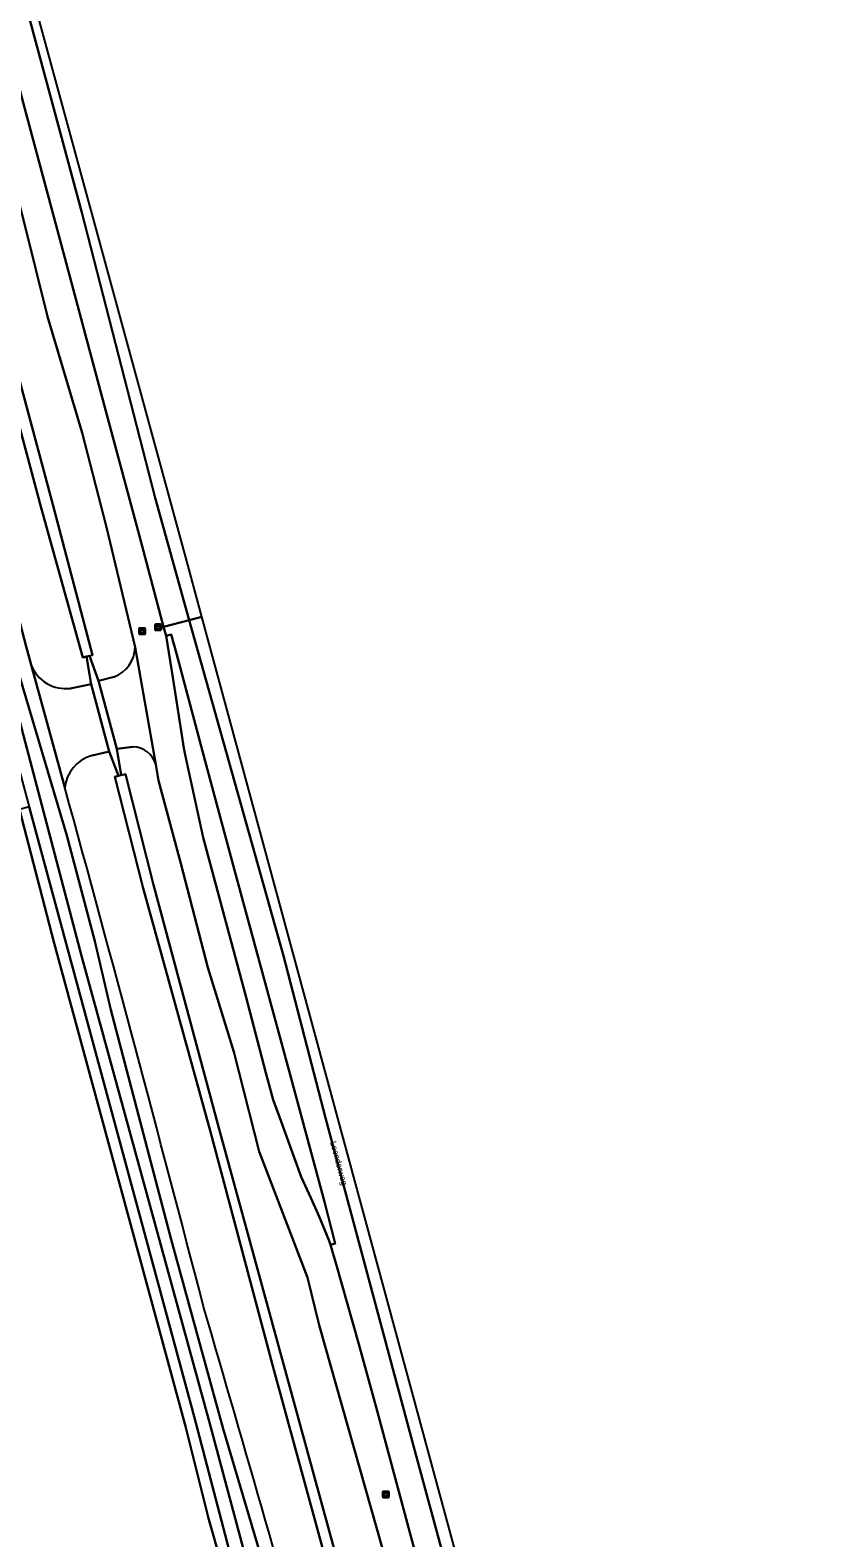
# Model space of a CAD drawing. Extents: x 162156 to 163172, y 378995 to 380779.
# Drawn here: x 162807.3 to 162935.4, y 380088.4 to 380333.8 of the extents above; entities that cross this region are included whole.
import ezdxf

# ---------------------------------------------------------------- set-up
doc = ezdxf.new("R2010")
doc.units = 0
for name, color, linetype in [('IMGEO_Berm_groen', 7, 'Continuous'), ('IMGEO_Groenvoorziening', 7, 'Continuous'), ('IMGEO_Muur', 7, 'Continuous'), ('IMGEO_Naaldbos', 7, 'Continuous'), ('IMGEO_Openbare_ruimte_label', 7, 'Continuous'), ('IMGEO_Rijbaan_lokaal_gesloten', 7, 'Continuous'), ('IMGEO_Rijbaan_lokaal_onverhard', 7, 'Continuous'), ('IMGEO_Rijbaan_regionaal_gesloten', 7, 'Continuous'), ('IMGEO_Wegwijzer', 7, 'Continuous')]:
    doc.layers.add(name, color=color, linetype=linetype)

msp = doc.modelspace()

# ---------------------------------------------------------------- linework, layer by layer
at = {"layer": 'IMGEO_Berm_groen'}
for points in [[(162794.77, 380347.98), (162799, 380332.96), (162802.18, 380318.49), (162806.33, 380302.5), (162810.15, 380287.19), (162815.78, 380268.27), (162819.72, 380252.92), (162824.4, 380233.35), (162827.76, 380214.25), (162828.22, 380211.65), (162831.86, 380198.18), (162836.23, 380181.26), (162840.44, 380167.5), (162844.58, 380151.28), (162852.47, 380130.79), (162854.36, 380123.05), (162864.7, 380086.48), (162869.2, 380069.9), (162880.27, 380030.3), (162885.8, 380009.88), (162894.02, 379977.91), (162894.82, 379974.81), (162899.22, 379955.87)], [(162842.43, 380176.6), (162835.45, 380202.41), (162832.56, 380215.85), (162832.33, 380216.92), (162831.77, 380220.44), (162830.51, 380228.44), (162829.43, 380235.22), (162829.03, 380236.7), (162825.25, 380250.82), (162819.58, 380271.99), (162813.55, 380294.48), (162806.62, 380320.37), (162800.79, 380342.1)], [(162917.61, 379909.32), (162910.58, 379935.34), (162903.48, 379962.19), (162894.41, 379995.63), (162889.22, 380014.47), (162884.39, 380032.32), (162875.97, 380063.72), (162870.69, 380083.46), (162863.82, 380109.09), (162860.82, 380119.94), (162857.11, 380132.94), (162856.21, 380136.12), (162855.96, 380136.76), (162854.36, 380140.73), (162852.99, 380143.75), (162851.45, 380147.17), (162847.93, 380156.76), (162846.88, 380159.68), (162845.69, 380164.1), (162842.43, 380176.6)]]:
    msp.add_lwpolyline(points, dxfattribs=at)
at = {"layer": 'IMGEO_Groenvoorziening'}
for points in [[(162734.13, 380481.79), (162738.94, 380462.93), (162755.08, 380399.61), (162794.83, 380252.85), (162795.6, 380250), (162807.15, 380207.37), (162834.02, 380108.17), (162847.39, 380056.99), (162849.58, 380050.07), (162853.05, 380036.53), (162855.7, 380027.53), (162859.06, 380014.99), (162859.82, 380012.91), (162860.3, 380010.25), (162863.33, 380000), (162875.93, 379953.56)], [(162813.85, 380226.67), (162817.23, 380227.35), (162816.46, 380231.84), (162815.9, 380231.68), (162809.1, 380256.05), (162785, 380346.14), (162773.55, 380387.66), (162773.94, 380387.47), (162777.21, 380394.95), (162776.75, 380395.21)], [(162824.4, 380233.35), (162819.72, 380252.92), (162815.78, 380268.27), (162810.15, 380287.19), (162806.33, 380302.5), (162802.18, 380318.49), (162799, 380332.96), (162794.77, 380347.98), (162789.8, 380363.38), (162782.45, 380390.83), (162779.72, 380393.58), (162778.95, 380394.01), (162774.38, 380387.23), (162775.96, 380386.08), (162803.17, 380285.72), (162810.98, 380256.6), (162817.46, 380232.08), (162816.98, 380231.95), (162818.41, 380227.87), (162820.97, 380228.53)], [(162766.3, 380383.5), (162801.29, 380253.8), (162806.64, 380233.47), (162807.47, 380230.47)], [(162812.97, 380210.53), (162807.47, 380230.47), (162806.64, 380233.47), (162801.29, 380253.8), (162766.3, 380383.5)], [(162771.24, 380358.92), (162778.52, 380332.03), (162782.46, 380315.75), (162787.62, 380297.4), (162792.42, 380276.74), (162796.52, 380260.82), (162798.6, 380253.4), (162804.6, 380231.95), (162813.27, 380202.73), (162817.83, 380185.51), (162820.47, 380174.33), (162830.29, 380136.99), (162838.72, 380106.16), (162845.72, 380082.59), (162848.03, 380072.7), (162850.82, 380063.54), (162873.07, 379986.28), (162876.41, 379973.93), (162879.54, 379963.77)], [(162877.81, 379945.48), (162877.93, 379942.99), (162877.84, 379940.5), (162876.06, 379930), (162869.52, 379903.66), (162857.79, 379858.93), (162852.22, 379836.57), (162855.95, 379839.98), (162859.94, 379851), (162864.32, 379866.72), (162869.74, 379887.62), (162878.52, 379925.93), (162880.46, 379936.12), (162880.89, 379940.36), (162878.53, 379959.46), (162877.4, 379963.09), (162875.48, 379970.32), (162872.22, 379980.62), (162850.44, 380055.19), (162836.52, 380107.17), (162815.65, 380183.14), (162803.81, 380228.27), (162800.75, 380239.27), (162797.43, 380253.23)], [(162827.76, 380214.25), (162824.4, 380233.35)], [(162807.47, 380230.47), (162812.97, 380210.53)], [(162820.97, 380228.53), (162818.41, 380227.87), (162821.41, 380216.81), (162824.02, 380217.14)], [(162817.21, 380215.67), (162820.17, 380216.39), (162817.23, 380227.35), (162813.85, 380226.67)], [(162891.3, 379949.82), (162884.94, 379975.43), (162878.71, 380000.53), (162868.08, 380038.13), (162857.7, 380076.5), (162846.96, 380115.76), (162836.68, 380154.47), (162825.7, 380194.15), (162821.09, 380212.25), (162821.68, 380212.41), (162820.17, 380216.39), (162817.21, 380215.67)], [(162824.02, 380217.14), (162821.41, 380216.81), (162822.15, 380212.53), (162822.81, 380212.7), (162827.41, 380194.67), (162838.08, 380154.93), (162859.43, 380077.09), (162869.82, 380038.83), (162880.45, 380000.89), (162886.92, 379975.98), (162893.55, 379950.48)], [(162935.38, 379790.49), (162929.16, 379811.21), (162923.52, 379831.46), (162920.05, 379843.16), (162910.96, 379872.62), (162909.01, 379881.44), (162906.14, 379899.21), (162904.56, 379914.07), (162902.22, 379931.42), (162899.22, 379955.87), (162894.82, 379974.81), (162894.02, 379977.91), (162885.8, 380009.88), (162880.27, 380030.3), (162869.2, 380069.9), (162864.7, 380086.48), (162854.36, 380123.05), (162852.47, 380130.79), (162844.58, 380151.28), (162840.44, 380167.5), (162836.23, 380181.26), (162831.86, 380198.18), (162828.22, 380211.65), (162827.76, 380214.25)], [(162893.55, 379950.48), (162886.92, 379975.98), (162880.45, 380000.89), (162869.82, 380038.83), (162859.43, 380077.09), (162838.08, 380154.93), (162827.41, 380194.67), (162822.81, 380212.7), (162822.15, 380212.53), (162821.68, 380212.41), (162821.09, 380212.25), (162825.7, 380194.15), (162836.68, 380154.47), (162846.96, 380115.76), (162857.7, 380076.5), (162868.08, 380038.13), (162878.71, 380000.53), (162884.94, 379975.43), (162891.3, 379949.82)]]:
    msp.add_lwpolyline(points, dxfattribs=at)
msp.add_lwpolyline([(162775.96, 380386.08), (162774.38, 380387.23), (162773.94, 380387.47), (162773.55, 380387.66), (162785, 380346.14), (162809.1, 380256.05), (162815.9, 380231.68), (162816.46, 380231.84), (162816.98, 380231.95), (162817.46, 380232.08), (162810.98, 380256.6), (162803.17, 380285.72)], close=True, dxfattribs=at)
for centre, radius, start, end in [((162819.03, 380233.54), 5.37, 291.2055, 358.0298), ((162819.03, 380233.54), 5.37, 291.2055, 358.0298), ((162813.16, 380232.76), 6.14, 201.9572, 276.5145), ((162813.16, 380232.76), 6.14, 201.9572, 276.5145), ((162824.02, 380213.28), 3.86, 14.6226, 90.0212), ((162824.02, 380213.28), 3.86, 14.6226, 90.0212), ((162818.9, 380209.95), 5.96, 106.4803, 174.4608), ((162818.9, 380209.95), 5.96, 106.4803, 174.4608), ((156261.77, 378414.57), 6792.91, 14.592707, 15.330545), ((156261.77, 378414.57), 6792.91, 14.592707, 15.330545), ((155605.64, 378014.13), 7532.04, 15.180091, 16.283276), ((155605.64, 378014.13), 7532.04, 15.180091, 16.283276)]:
    msp.add_arc(centre, radius, start, end, dxfattribs=at)
at = {"layer": 'IMGEO_Muur'}
msp.add_lwpolyline([(162822.15, 380212.53), (162821.41, 380216.81), (162818.41, 380227.87), (162816.98, 380231.95), (162816.46, 380231.84), (162817.23, 380227.35), (162820.17, 380216.39), (162821.68, 380212.41)], close=True, dxfattribs=at)
at = {"layer": 'IMGEO_Naaldbos'}
msp.add_lwpolyline([(162838.54, 380083.95), (162836.29, 380091.77), (162832.66, 380106.4), (162811.23, 380185.22), (162805.6, 380206.95), (162776.26, 380199.6), (162758.21, 380171.26), (162779.59, 380093.44), (162780.64, 380093.58), (162806.22, 380000)], dxfattribs=at)
at = {"layer": 'IMGEO_Rijbaan_lokaal_gesloten'}
msp.add_lwpolyline([(162840.57, 380197.09), (162835.6, 380215.62), (162831.11, 380232.32), (162830.27, 380235.45), (162829.43, 380235.22), (162830.51, 380228.44), (162831.77, 380220.44), (162832.33, 380216.92), (162832.56, 380215.85), (162835.45, 380202.41), (162842.43, 380176.6), (162845.69, 380164.1), (162846.88, 380159.68), (162847.93, 380156.76), (162851.45, 380147.17), (162852.99, 380143.75), (162854.36, 380140.73), (162855.96, 380136.76), (162856.21, 380136.12), (162856.98, 380136.34), (162855.2, 380143.13), (162852.13, 380154.55), (162849.56, 380163.99), (162844.9, 380181.12)], close=True, dxfattribs=at)
msp.add_lwpolyline([(162847.39, 380056.99), (162834.02, 380108.17), (162807.15, 380207.37), (162805.6, 380206.95), (162811.23, 380185.22), (162832.66, 380106.4), (162836.29, 380091.77), (162838.54, 380083.95)], dxfattribs=at)
at = {"layer": 'IMGEO_Rijbaan_lokaal_onverhard'}
for points in [[(162887.73, 379923.86), (162885.3, 379937.58), (162879.54, 379963.77), (162876.41, 379973.93), (162873.07, 379986.28), (162850.82, 380063.54), (162848.03, 380072.7), (162845.72, 380082.59), (162838.72, 380106.16), (162830.29, 380136.99), (162820.47, 380174.33), (162817.83, 380185.51), (162813.27, 380202.73), (162804.6, 380231.95), (162798.6, 380253.4), (162796.52, 380260.82), (162792.42, 380276.74), (162787.62, 380297.4), (162782.46, 380315.75), (162778.52, 380332.03), (162771.24, 380358.92), (162764.08, 380387.55), (162762.98, 380391.94), (162737.51, 380495.43)], [(162765.42, 380371.74), (162775.36, 380333.72), (162786.53, 380293.52), (162791.92, 380273.3), (162797.43, 380253.23), (162800.75, 380239.27), (162803.81, 380228.27), (162815.65, 380183.14), (162836.52, 380107.17), (162850.44, 380055.19), (162872.22, 379980.62), (162875.48, 379970.32), (162877.4, 379963.09)]]:
    msp.add_lwpolyline(points, dxfattribs=at)
at = {"layer": 'IMGEO_Rijbaan_regionaal_gesloten'}
msp.add_lwpolyline([(162835.27, 380238.32), (162832.98, 380246.79), (162737.06, 380598.14), (162686.38, 380740.14), (162683.4, 380739.7), (162691.09, 380720.33), (162695.16, 380708.96), (162706.16, 380680.3), (162730.73, 380611.09), (162744.15, 380567.96), (162763.14, 380500.1), (162770.9, 380471.58), (162776.29, 380450.02), (162815.72, 380304.13), (162827.68, 380257.65), (162833.19, 380237.78)], close=True, dxfattribs=at)
for points in [[(162800.79, 380342.1), (162806.62, 380320.37), (162813.55, 380294.48), (162819.58, 380271.99), (162825.25, 380250.82), (162829.03, 380236.7), (162833.19, 380237.78), (162827.68, 380257.65), (162815.72, 380304.13), (162776.29, 380450.02)], [(162911.89, 379955.93), (162835.27, 380238.32), (162833.19, 380237.78), (162848.55, 380183.16), (162855.4, 380156.79), (162869.91, 380102.56), (162884.75, 380048.07), (162892.49, 380021.3), (162903.17, 379980.04), (162910.18, 379953.87)], [(162884.75, 380048.07), (162869.91, 380102.56), (162855.4, 380156.79), (162848.55, 380183.16), (162833.19, 380237.78), (162829.03, 380236.7), (162829.43, 380235.22), (162830.27, 380235.45), (162831.11, 380232.32), (162835.6, 380215.62), (162840.57, 380197.09), (162844.9, 380181.12), (162849.56, 380163.99), (162852.13, 380154.55), (162855.2, 380143.13), (162856.98, 380136.34), (162856.21, 380136.12), (162857.11, 380132.94), (162860.82, 380119.94), (162863.82, 380109.09), (162870.69, 380083.46)]]:
    msp.add_lwpolyline(points, dxfattribs=at)
at = {"layer": 'IMGEO_Wegwijzer'}
for p, q in [((162825.05, 380235.57), (162825.05, 380236.37)), ((162825.05, 380236.37), (162825.05, 380235.57)), ((162825.15, 380236.47), (162825.94, 380236.47)), ((162825.94, 380236.47), (162825.15, 380236.47)), ((162825.94, 380235.47), (162825.15, 380235.47)), ((162825.15, 380235.47), (162825.94, 380235.47)), ((162826.04, 380236.37), (162826.04, 380235.57)), ((162826.04, 380235.57), (162826.04, 380236.37)), ((162827.64, 380236.21), (162827.64, 380237.01)), ((162827.64, 380237.01), (162827.64, 380236.21)), ((162827.74, 380237.11), (162828.53, 380237.11)), ((162828.53, 380237.11), (162827.74, 380237.11)), ((162828.53, 380236.11), (162827.74, 380236.11)), ((162827.74, 380236.11), (162828.53, 380236.11)), ((162828.63, 380237.01), (162828.63, 380236.21)), ((162828.63, 380236.21), (162828.63, 380237.01)), ((162864.72, 380095.09), (162864.72, 380095.89)), ((162864.72, 380095.89), (162864.72, 380095.09)), ((162864.82, 380095.99), (162865.61, 380095.99)), ((162865.61, 380095.99), (162864.82, 380095.99)), ((162865.71, 380095.89), (162865.71, 380095.09)), ((162865.71, 380095.09), (162865.71, 380095.89)), ((162865.61, 380094.99), (162864.82, 380094.99)), ((162864.82, 380094.99), (162865.61, 380094.99))]:
    msp.add_line(p, q, dxfattribs=at)
for points in [[(162825.15, 380236.2), (162825.94, 380236.2), (162825.94, 380235.74), (162825.15, 380235.74), (162825.15, 380236.2)], [(162825.22, 380236.14), (162825.22, 380235.8), (162825.88, 380235.8), (162825.88, 380236.14), (162825.22, 380236.14)], [(162827.74, 380236.84), (162828.53, 380236.84), (162828.53, 380236.37), (162827.74, 380236.37), (162827.74, 380236.84)], [(162827.81, 380236.77), (162827.81, 380236.44), (162828.47, 380236.44), (162828.47, 380236.77), (162827.81, 380236.77)], [(162864.82, 380095.73), (162865.61, 380095.73), (162865.61, 380095.26), (162864.82, 380095.26), (162864.82, 380095.73)], [(162864.89, 380095.66), (162864.89, 380095.33), (162865.54, 380095.33), (162865.54, 380095.66), (162864.89, 380095.66)]]:
    msp.add_lwpolyline(points, dxfattribs=at)
for centre, start, end in [((162825.15, 380236.37), 90, 180), ((162825.15, 380236.37), 90, 180), ((162825.15, 380235.57), 180, 270), ((162825.15, 380235.57), 180, 270), ((162825.94, 380236.37), 0, 90), ((162825.94, 380236.37), 360, 90), ((162825.94, 380235.57), 270, 0), ((162825.94, 380235.57), 270, 0), ((162827.74, 380237.01), 90, 180), ((162827.74, 380237.01), 90, 180), ((162827.74, 380236.21), 180, 270), ((162827.74, 380236.21), 180, 270), ((162828.53, 380237.01), 0, 90), ((162828.53, 380237.01), 360, 90), ((162828.53, 380236.21), 270, 0), ((162828.53, 380236.21), 270, 0), ((162864.82, 380095.89), 90, 180), ((162864.82, 380095.89), 90, 180), ((162865.61, 380095.89), 0, 90), ((162865.61, 380095.89), 360, 90), ((162864.82, 380095.09), 180, 270), ((162864.82, 380095.09), 180, 270), ((162865.61, 380095.09), 270, 0), ((162865.61, 380095.09), 270, 0)]:
    msp.add_arc(centre, 0.1, start, end, dxfattribs=at)

# ---------------------------------------------------------------- texts
at = {"layer": 'IMGEO_Openbare_ruimte_label'}
msp.add_text('Leenderweg', height=1, rotation=285.1345, dxfattribs=at).set_placement((162856.12, 380152.81))

doc.saveas('drawing.dxf')
